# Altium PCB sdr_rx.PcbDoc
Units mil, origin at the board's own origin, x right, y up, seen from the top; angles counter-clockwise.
Board outline 6000 x 4000 mil, 2 copper layers (Top Layer, Bottom Layer); 9 components, 22 nets, 293 pads, 0 vias.
Unrouted connection lines stored in the file: 7.
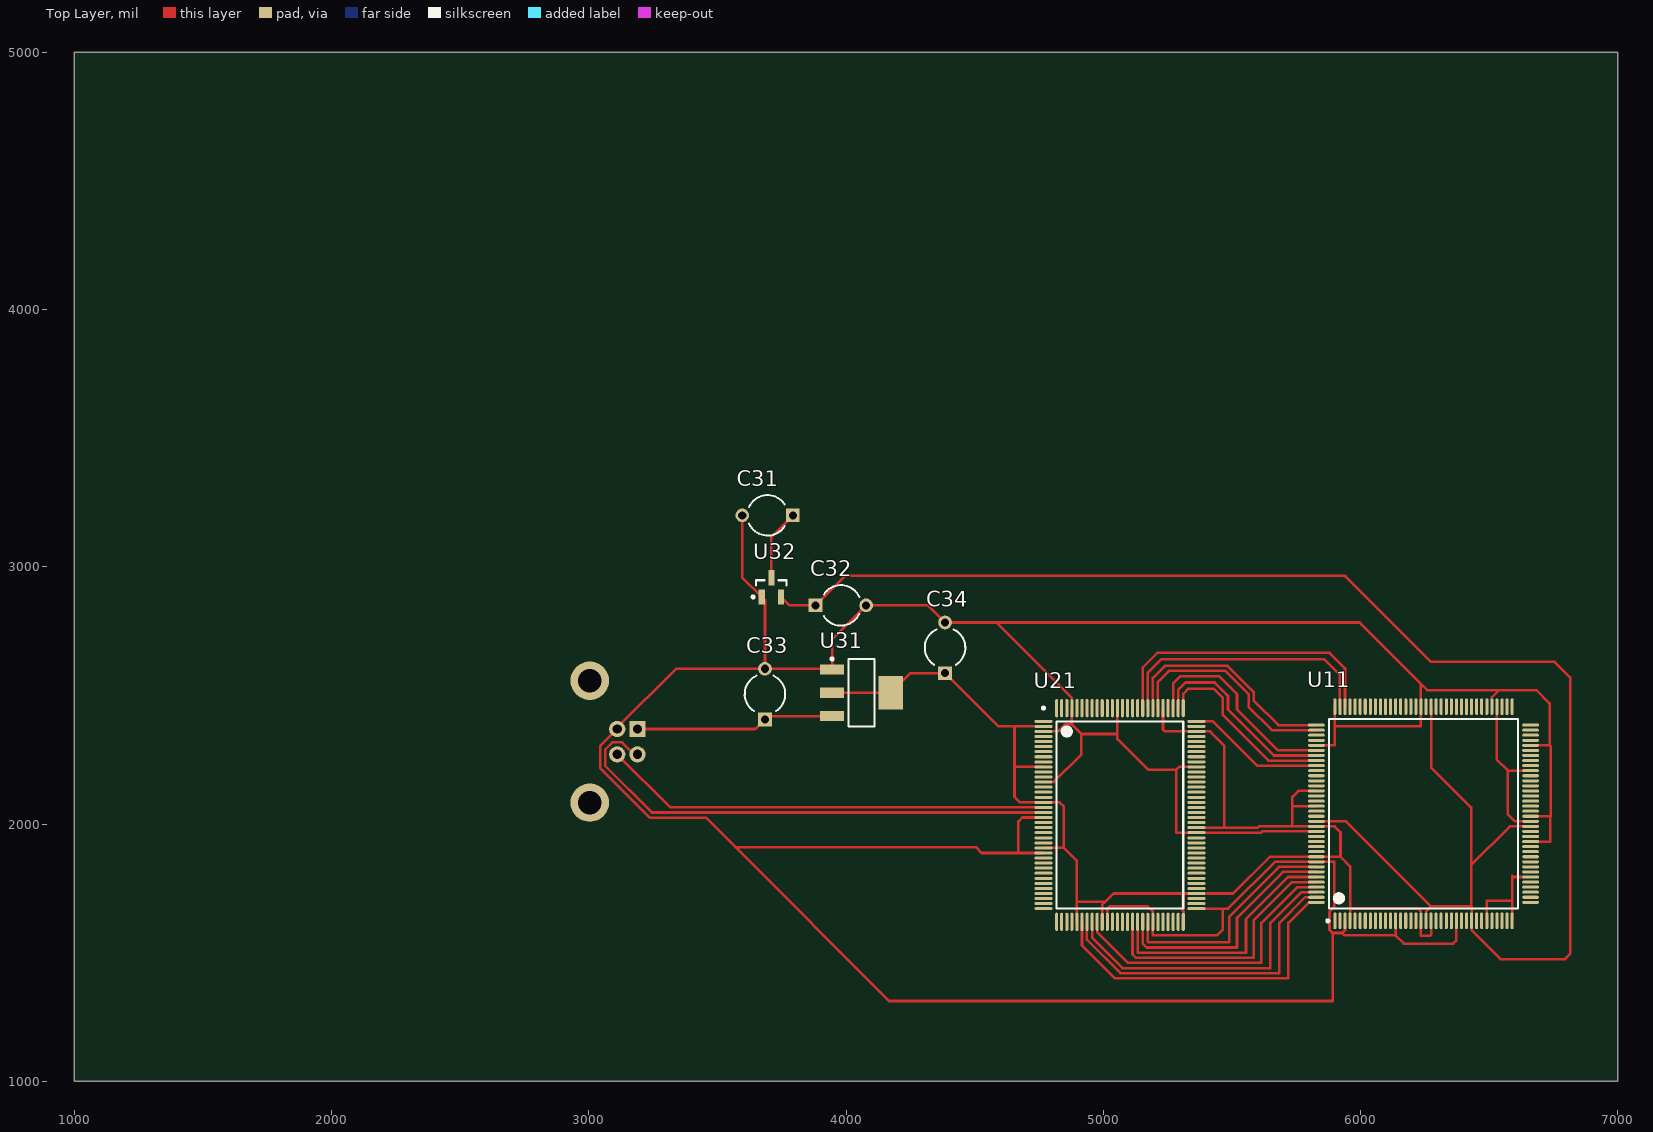
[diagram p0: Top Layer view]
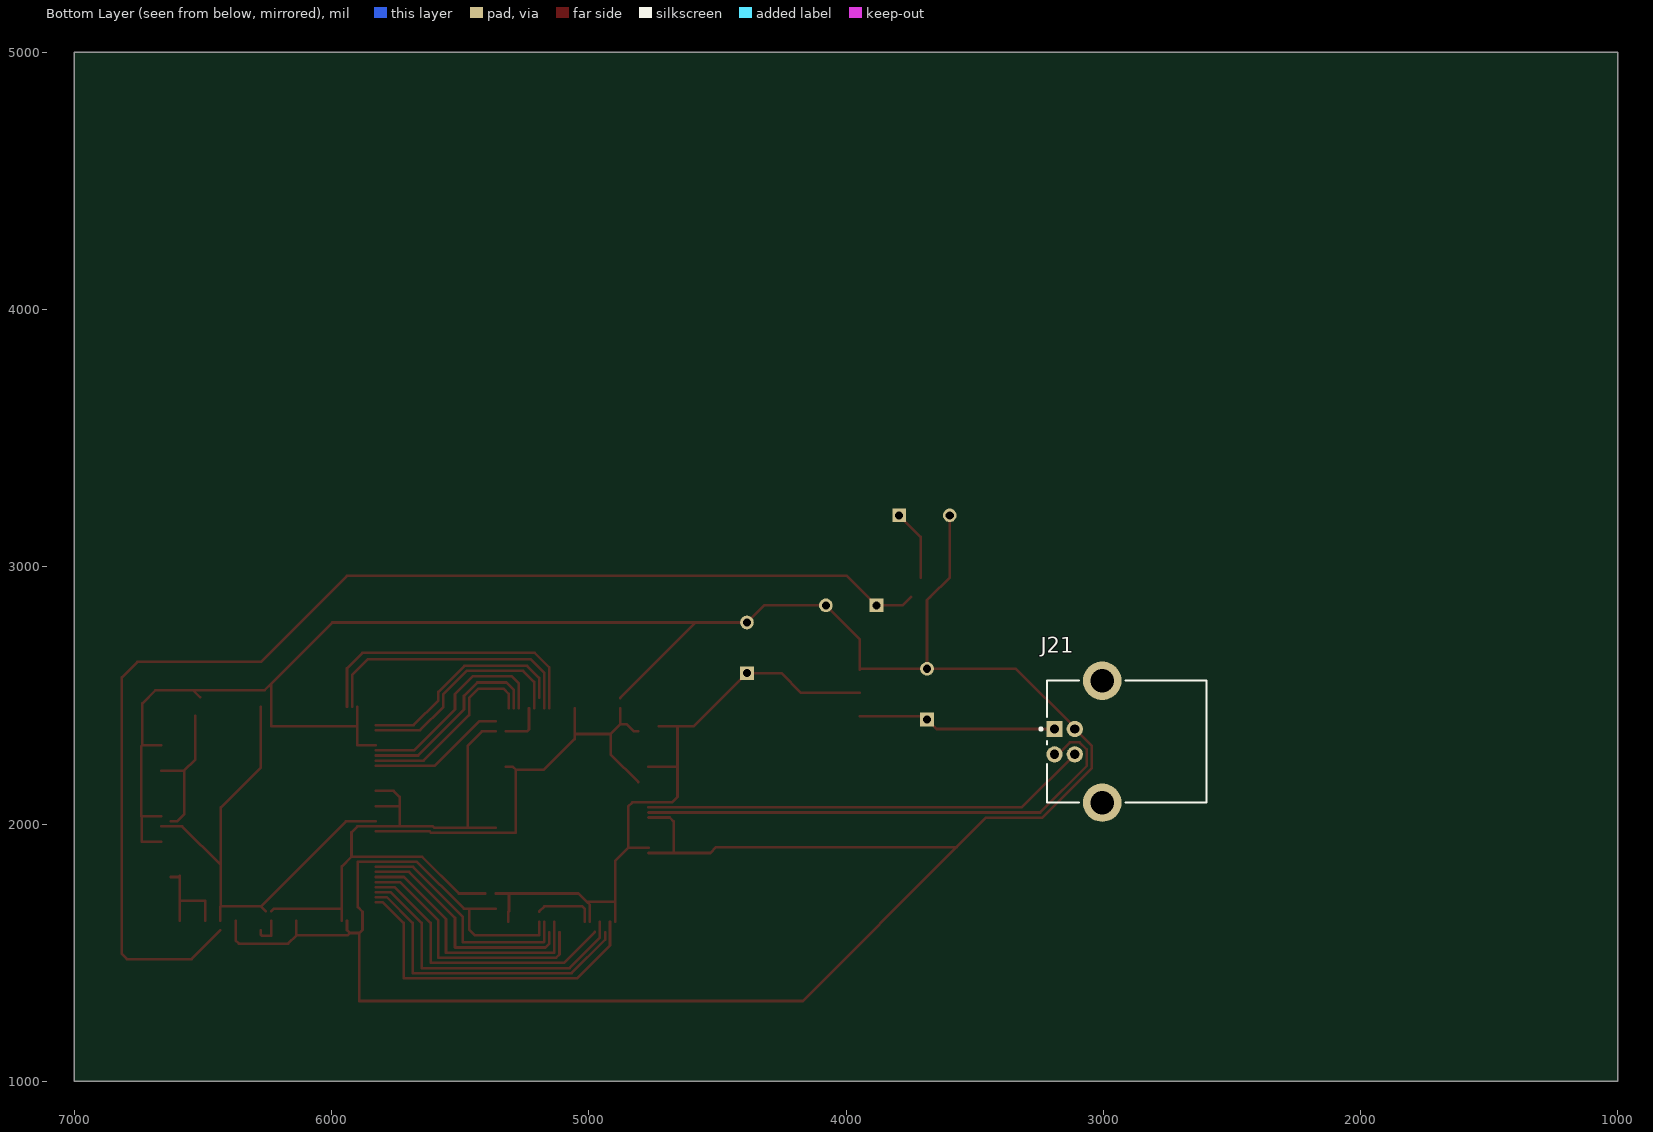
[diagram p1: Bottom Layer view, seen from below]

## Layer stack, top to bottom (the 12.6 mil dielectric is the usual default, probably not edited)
Top Layer: signal copper 1.4
Dielectric: dielectric 12.6, FR-4, Dk 4.8
Bottom Layer: signal copper 1.4

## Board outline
1000,1000 7000,1000 7000,5000 1000,5000

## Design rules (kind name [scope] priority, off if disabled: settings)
Clearance [All] p1: gap=10
PolygonConnect [All] p1: connectstyle=Relief reliefconductorwidth=10 reliefentries=4 polygonreliefangle="90 Angle"
RoomDefinition usbif [InComponentClass('usbif')] p1: confinementstyle=ConfineIn formatcopy=TRUE lockcomponents=FALSE outline 7045,2595 7745,2595 7745,3635 7045,3635
RoomDefinition power [InComponentClass('power')] p2: confinementstyle=ConfineIn formatcopy=TRUE lockcomponents=FALSE outline 7045,2145 9430,2145 9430,2545 7045,2545
RoomDefinition fpga [InComponentClass('fpga')] p3: confinementstyle=ConfineIn formatcopy=TRUE lockcomponents=FALSE outline 7045,1055 8185,1055 8185,2095 7045,2095
RoutingVias [All] p1: holewidth=28 width=50 viastyle="Through Hole" minholewidth=28 minwidth=50 maxholewidth=28 maxwidth=50
SilkscreenOverComponentPads [All] p1: minsilkscreentomaskgap=10
SolderMaskExpansion [All] p1: expansion=4
Width [All] p1: maxlimit=10 minlimit=10 preferedwidth=10
27 further rules are at their usual default settings.

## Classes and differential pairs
component class usbif: J21 U21
component class power: C31 C32 C33 C34 U31 U32

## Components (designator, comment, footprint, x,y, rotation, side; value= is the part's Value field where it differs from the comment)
C31 "Cap2" CAPR5-4X5 3695,3200 r180 top
C32 "Cap2" CAPR5-4X5 3980,2850 r0 top
C33 "Cap2" CAPR5-4X5 3685,2505 r90 top
C34 "Cap2" CAPR5-4X5 4385,2685 r90 top
J21 "787780-1" 787780 3150,2320 r180 bottom
U11 "XC6SLX9-2TQG144" TSQFP50P2200X2200X160-144N 6245,2040 r90 top
U21 "CY7C68014A-128AXC" A128_N 5065,2035 r0 top
U31 "TLV1117" SOT230P700X180-4N 4060,2510 r0 top
U32 "MCP1700T-1202E/TT" SOT-23-TT3_N 3710,2920 r90 top

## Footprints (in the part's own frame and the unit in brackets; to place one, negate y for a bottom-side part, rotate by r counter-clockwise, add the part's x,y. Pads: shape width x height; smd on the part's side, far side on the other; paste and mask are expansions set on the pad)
787780 [mm] "Connector; USB1.1, Type B, Thru-Hole; 4 Position; Right Angle"
  rect 1.6x1.6 hole 0.92: 1(-1,1.25)
  round 1.6 hole 0.92: 2(-1,-1.25) 3(1,-1.25) 4(1,1.25)
  round 3.8 hole 2.3: 5(3.71,6.02) 6(3.71,-6.02)
  silkscreen extent -2.48,-6.02 13.99,6.02
A128_N [mm] "Thin QFP, 128-Leads, Body 20x14 mm, Pitch 0.5mm, IPC Medium Density"
  oval 1.8x0.3 smd: 1(-7.55,9.25) 2(-7.55,8.75) 3(-7.55,8.25) 4(-7.55,7.75) 5(-7.55,7.25) 6(-7.55,6.75) 7(-7.55,6.25) 8(-7.55,5.75) 9(-7.55,5.25) 10(-7.55,4.75) 11(-7.55,4.25) 12(-7.55,3.75) 13(-7.55,3.25) 14(-7.55,2.75) 15(-7.55,2.25) 16(-7.55,1.75) 17(-7.55,1.25) 18(-7.55,0.75) 19(-7.55,0.25) 20(-7.55,-0.25) 21(-7.55,-0.75) 22(-7.55,-1.25) 23(-7.55,-1.75) 24(-7.55,-2.25) 25(-7.55,-2.75) 26(-7.55,-3.25) 27(-7.55,-3.75) 28(-7.55,-4.25) 29(-7.55,-4.75) 30(-7.55,-5.25) 31(-7.55,-5.75) 32(-7.55,-6.25) 33(-7.55,-6.75) 34(-7.55,-7.25) 35(-7.55,-7.75) 36(-7.55,-8.25) 37(-7.55,-8.75) 38(-7.55,-9.25) 65(7.55,-9.25) 66(7.55,-8.75) 67(7.55,-8.25) 68(7.55,-7.75) 69(7.55,-7.25) 70(7.55,-6.75) 71(7.55,-6.25) 72(7.55,-5.75) 73(7.55,-5.25) 74(7.55,-4.75) 75(7.55,-4.25) 76(7.55,-3.75) 77(7.55,-3.25) 78(7.55,-2.75) 79(7.55,-2.25) 80(7.55,-1.75) 81(7.55,-1.25) 82(7.55,-0.75) 83(7.55,-0.25) 84(7.55,0.25) 85(7.55,0.75) 86(7.55,1.25) 87(7.55,1.75) 88(7.55,2.25) 89(7.55,2.75) 90(7.55,3.25) 91(7.55,3.75) 92(7.55,4.25) 93(7.55,4.75) 94(7.55,5.25) 95(7.55,5.75) 96(7.55,6.25) 97(7.55,6.75) 98(7.55,7.25) 99(7.55,7.75) 100(7.55,8.25) 101(7.55,8.75) 102(7.55,9.25)
  oval 0.3x1.8 smd: 39(-6.25,-10.55) 40(-5.75,-10.55) 41(-5.25,-10.55) 42(-4.75,-10.55) 43(-4.25,-10.55) 44(-3.75,-10.55) 45(-3.25,-10.55) 46(-2.75,-10.55) 47(-2.25,-10.55) 48(-1.75,-10.55) 49(-1.25,-10.55) 50(-0.75,-10.55) 51(-0.25,-10.55) 52(0.25,-10.55) 53(0.75,-10.55) 54(1.25,-10.55) 55(1.75,-10.55) 56(2.25,-10.55) 57(2.75,-10.55) 58(3.25,-10.55) 59(3.75,-10.55) 60(4.25,-10.55) 61(4.75,-10.55) 62(5.25,-10.55) 63(5.75,-10.55) 64(6.25,-10.55) 103(6.25,10.55) 104(5.75,10.55) 105(5.25,10.55) 106(4.75,10.55) 107(4.25,10.55) 108(3.75,10.55) 109(3.25,10.55) 110(2.75,10.55) 111(2.25,10.55) 112(1.75,10.55) 113(1.25,10.55) 114(0.75,10.55) 115(0.25,10.55) 116(-0.25,10.55) 117(-0.75,10.55) 118(-1.25,10.55) 119(-1.75,10.55) 120(-2.25,10.55) 121(-2.75,10.55) 122(-3.25,10.55) 123(-3.75,10.55) 124(-4.25,10.55) 125(-4.75,10.55) 126(-5.25,10.55) 127(-5.75,10.55) 128(-6.25,10.55)
  silkscreen extent -7.67,-9.25 6.25,10.67, body extent -7,-10 7,10, height 1.6
CAPR5-4X5 [mm] "Capacitor; 2 Leads"
  rect 1.35x1.35 hole 0.8: 1(-2.5,0)
  round 1.35 hole 0.8: 2(2.5,0)
  silkscreen extent -1.69,-2 1.82,2
SOT230P700X180-4N [mm] "SOT223, 4-Leads, Body 6.7x7.3mm (max), Pitch 2.30mm, IPC Medium Density"
  rect 2.4x1 smd: 1(-2.9,2.3) 2(-2.9,0) 3(-2.9,-2.3)
  rect 2.4x3.3 smd: 4(2.9,0)
  silkscreen extent -3.02,-3.35 1.3,3.47, body extent -1.85,-3.35 1.85,3.35, height 1.8
SOT-23-TT3_N [mm] "SOT23, 3-Leads, Body 2.9x1.3mm, Pitch 0.95mm, Lead Span 2.4mm, IPC Medium Density"
  rect 1.5x0.6 smd: 1(-0.95,0.95) 2(-0.95,-0.95) 3(0.95,0)
  silkscreen extent -1.07,-1.5 0.7,1.92, body extent -0.7,-1.5 0.7,1.5, height 1.12
TSQFP50P2200X2200X160-144N [mm] "TSQFP, 144-Leads, Body 22.0x22.0mm (max), Pitch 0.50mm, IPC Medium Density"
  oval 1.65x0.3 smd: 1(-10.575,8.75) 2(-10.575,8.25) 3(-10.575,7.75) 4(-10.575,7.25) 5(-10.575,6.75) 6(-10.575,6.25) 7(-10.575,5.75) 8(-10.575,5.25) 9(-10.575,4.75) 10(-10.575,4.25) 11(-10.575,3.75) 12(-10.575,3.25) 13(-10.575,2.75) 14(-10.575,2.25) 15(-10.575,1.75) 16(-10.575,1.25) 17(-10.575,0.75) 18(-10.575,0.25) 19(-10.575,-0.25) 20(-10.575,-0.75) 21(-10.575,-1.25) 22(-10.575,-1.75) 23(-10.575,-2.25) 24(-10.575,-2.75) 25(-10.575,-3.25) 26(-10.575,-3.75) 27(-10.575,-4.25) 28(-10.575,-4.75) 29(-10.575,-5.25) 30(-10.575,-5.75) 31(-10.575,-6.25) 32(-10.575,-6.75) 33(-10.575,-7.25) 34(-10.575,-7.75) 35(-10.575,-8.25) 36(-10.575,-8.75) 73(10.575,-8.75) 74(10.575,-8.25) 75(10.575,-7.75) 76(10.575,-7.25) 77(10.575,-6.75) 78(10.575,-6.25) 79(10.575,-5.75) 80(10.575,-5.25) 81(10.575,-4.75) 82(10.575,-4.25) 83(10.575,-3.75) 84(10.575,-3.25) 85(10.575,-2.75) 86(10.575,-2.25) 87(10.575,-1.75) 88(10.575,-1.25) 89(10.575,-0.75) 90(10.575,-0.25) 91(10.575,0.25) 92(10.575,0.75) 93(10.575,1.25) 94(10.575,1.75) 95(10.575,2.25) 96(10.575,2.75) 97(10.575,3.25) 98(10.575,3.75) 99(10.575,4.25) 100(10.575,4.75) 101(10.575,5.25) 102(10.575,5.75) 103(10.575,6.25) 104(10.575,6.75) 105(10.575,7.25) 106(10.575,7.75) 107(10.575,8.25) 108(10.575,8.75)
  oval 0.3x1.65 smd: 37(-8.75,-10.575) 38(-8.25,-10.575) 39(-7.75,-10.575) 40(-7.25,-10.575) 41(-6.75,-10.575) 42(-6.25,-10.575) 43(-5.75,-10.575) 44(-5.25,-10.575) 45(-4.75,-10.575) 46(-4.25,-10.575) 47(-3.75,-10.575) 48(-3.25,-10.575) 49(-2.75,-10.575) 50(-2.25,-10.575) 51(-1.75,-10.575) 52(-1.25,-10.575) 53(-0.75,-10.575) 54(-0.25,-10.575) 55(0.25,-10.575) 56(0.75,-10.575) 57(1.25,-10.575) 58(1.75,-10.575) 59(2.25,-10.575) 60(2.75,-10.575) 61(3.25,-10.575) 62(3.75,-10.575) 63(4.25,-10.575) 64(4.75,-10.575) 65(5.25,-10.575) 66(5.75,-10.575) 67(6.25,-10.575) 68(6.75,-10.575) 69(7.25,-10.575) 70(7.75,-10.575) 71(8.25,-10.575) 72(8.75,-10.575) 109(8.75,10.575) 110(8.25,10.575) 111(7.75,10.575) 112(7.25,10.575) 113(6.75,10.575) 114(6.25,10.575) 115(5.75,10.575) 116(5.25,10.575) 117(4.75,10.575) 118(4.25,10.575) 119(3.75,10.575) 120(3.25,10.575) 121(2.75,10.575) 122(2.25,10.575) 123(1.75,10.575) 124(1.25,10.575) 125(0.75,10.575) 126(0.25,10.575) 127(-0.25,10.575) 128(-0.75,10.575) 129(-1.25,10.575) 130(-1.75,10.575) 131(-2.25,10.575) 132(-2.75,10.575) 133(-3.25,10.575) 134(-3.75,10.575) 135(-4.25,10.575) 136(-4.75,10.575) 137(-5.25,10.575) 138(-5.75,10.575) 139(-6.25,10.575) 140(-6.75,10.575) 141(-7.25,10.575) 142(-7.75,10.575) 143(-8.25,10.575) 144(-8.75,10.575)
  silkscreen extent -10.7,-9.35 9.35,9.57, body extent -10,-10 10,10, height 1.6

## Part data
C31 C32 C33 C34: "Capacitor"
J21: "USB 1.1, Right Angle, Thru-Hole, B Type, Receptacle, 4 Position, Black"
U21: "EZ-USB FX2LP USB Microcontroller Ideal for Battery Powered Applications,16K RAM, 40 I/Os, 128-Pin TQFP, Pb-Free, Commercial Grade"
U32: "Low Quiescent Current LDO, 3-Pin SOT-23, Extended Temperature, Tape and Reel"

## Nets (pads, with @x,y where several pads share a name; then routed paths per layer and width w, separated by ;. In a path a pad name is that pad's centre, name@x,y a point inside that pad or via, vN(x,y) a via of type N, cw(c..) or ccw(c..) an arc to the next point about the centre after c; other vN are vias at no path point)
1V2: C32.1 U11.19 U11.28 U11.52 U11.89 U11.128 U32.2 | length 6762.7
  Top Layer w10: U32.2 3780,2850 C32.1 3996.57,2965 5940,2965 6274.53,2630.47 6754.53,2630.47 6815,2570 6815,1495 6795,1475 6544.21,1475 6432.01,1587.21 ; U11.128 5944.25,2010.47 6274.73,1680 ; 6255.16,1660.43 6274.73,1680 ; U11.89 6274.53,2220.47 6430,2065 6430,1840 ; U11.28 6432.01,1677.99 6430,1680 ; U11.52 6580.79,1990.79 6430,1840 ; 6274.73,1680 6430,1680 ; 6430,1680 6430,1840
3V3: C34.1 U11.4 U11.18 U11.20 U11.31 U11.36 U11.42 U11.53 U11.63 U11.76 U11.86 U11.90 U11.103 U11.122 U11.125 U11.129 U11.135 U21.2 U21.10 U21.17 U21.26 U21.43 U21.48 U21.64 U21.68 U21.81 U21.100 U21.107 U31.2 U31.4 | length 6503.5
  Top Layer w10: U31.2 U31.4 4250.75,2586.57 C34.1 4592.09,2379.49 4655,2379.49 ; 4728.35,2379.49 4655,2379.49 ; U21.26 4847.05,1907.05 ; U21.10 4657.01,2222.01 4655,2220 ; U21.43 4897.68,1697.68 ; U21.48 4996.1,1686.1 5007.68,1697.68 ; U21.107 5232.32,2367.68 5240.2,2359.8 5322.84,2359.8 ; U21.64@5312.28,1619.65 5312.28,1657.83 5310.12,1660 5310.12,1729.88 ; U21.68 5310.12,1729.88 ; U21.81 5600.79,1985.79 5605.79,1990.79 U11.129 5899.21,1990.79 5922.32,1967.68 5922.32,1872.68 ; U21.100 5415.2,2359.8 5470,2305 5470,1986.1 ; 5401.65,1729.88 5504.88,1729.88 5647.68,1872.68 U11.135 5922.32,1872.68 ; 5735,1991.1 5735,2070 ; U11.125 5735.47,2069.53 5735,2070 ; U11.122 5758.58,2128.58 5735,2105 5735,2070 ; U11.4 5959.57,1669.57 ; U11.18 6235.16,1565.16 6270.16,1565.16 6274.53,1569.53 6274.53,1587.21 ; 6235.16,1660.12 6224.13,1671.14 5961.14,1671.14 5959.57,1669.57 ; U11.31 6491.06,1701.06 6588.43,1701.06 6589.49,1700 ; 6530.43,2419.88 6530.43,2249.57 6572.68,2207.32 ; U11.36 6589.49,1700 ; 6624.57,2010.79 6599.21,2010.79 6572.68,2037.32 6572.68,2207.32 ; 6624.88,1793.94 6595.04,1793.94 6589.49,1799.49 6589.49,1700 ; U11.63 6572.68,2207.32 ; 4655,2220 4655,2379.49 ; 4655,2220 4655,2105 4675.79,2084.21 U21.17 4830.79,2084.21 4847.05,2067.95 4847.05,1907.05 ; 4847.05,1907.05 4897.68,1856.42 4897.68,1697.68 ; 4897.68,1697.68 5007.68,1697.68 ; 5007.68,1697.68 5039.88,1729.88 5310.12,1729.88 ; 5922.32,1872.68 5959.57,1835.43 5959.57,1669.57
DATA0: U11.144 U21.44 | length 1304.5
  Top Layer w10: U21.44 4917.36,1527.64 5045,1400 5720,1400 5720,1615 5800.51,1695.51 U11.144
DATA1: U11.143 U21.45 | length 1212.2
  Top Layer w10: 4936.73,1579.92 4936.73,1549.98 5066.72,1420 5685,1420 5685,1615 5785.2,1715.2 U11.143
DATA2: U11.142 U21.46 | length 1207
  Top Layer w10: U21.46 4956.73,1558.27 5075,1440 5650,1440 5650,1615 5769.88,1734.88 U11.142
DATA3: U11.141 U21.47 | length 1114.9
  Top Layer w10: 4976.42,1580.24 5096.66,1460 5615,1460 5615,1615 5754.57,1754.57 U11.141
DATA4: U11.140 U21.54 | length 1014
  Top Layer w10: 5113.9,1579.92 5113.9,1492.82 5126.72,1480 5585,1480 5585,1625 5734.25,1774.25 U11.140
DATA5: U11.139 U21.55 | length 1011.7
  Top Layer w10: U21.55 5133.9,1501.1 5135,1500 5555,1500 5555,1630 5718.94,1793.94 U11.139
DATA6: U11.138 U21.56 | length 915.5
  Top Layer w10: 5153.27,1579.92 5153.27,1534.98 5168.25,1520 5520,1520 5520,1635 5698.62,1813.62 U11.138
DATA7: U11.137 U21.57 | length 913.2
  Top Layer w10: U21.57 5173.27,1543.27 5176.54,1540 5490,1540 5490,1640 5683.31,1833.31 U11.137
DATA8: U11.117 U21.102 | length 537.7
  Top Layer w10: U21.102 5425.83,2399.17 5597.99,2227.01 U11.117
DATA9: U11.116 U21.103 | length 735.5
  Top Layer w10: U21.103 5311.06,2506.06 5330,2525 5430,2525 5465,2490 5465,2423.39 5641.69,2246.69 U11.116
DATA10: U11.115 U21.104 | length 768.9
  Top Layer w10: U21.104 5291.38,2521.38 5320,2550 5433.28,2550 5485,2498.28 5485,2445 5663.62,2266.38 U11.115
DATA11: U11.114 U21.105 | length 819.9
  Top Layer w10: U21.105 5271.69,2546.69 5300,2575 5450,2575 5520,2505 5520,2445 5678.94,2286.06 U11.114
DMINUS: J21.2 U21.19 | length 1998.6
  Top Layer w10: J21.2 3176.39,2270.79 3129.89,2317.28 3091.37,2317.28 3064.13,2290.05 3064.13,2225.87 3245.16,2044.84 U21.19
DPLUS: J21.3 U21.18 | length 1742.6
  Top Layer w10: J21.3 3316.89,2064.53 U21.18
GND: C31.2 C32.2 C33.2 C34.2 J21.4 U11.3 U11.13 U11.25 U11.49 U11.54 U11.68 U11.77 U11.91 U11.96 U11.108 U11.113 U11.130 U11.136 U21.3 U21.13 U21.20 U21.27 U21.49 U21.58 U21.65 U21.80 U21.93 U21.116 U21.125 U31.1 U32.1 | length 15783.1
  Top Layer w10: C31.2 3596.57,2958.62 U32.1 3685,2870.2 C33.2 ; U21.27 4670,1887.36 ; U21.20 4685.16,2025.16 4670,2010 4670,1887.36 ; 4807.16,2162.95 4915,2270.79 4915,2350 ; 4807.16,2359.8 4824.8,2359.8 4852.01,2387.01 4877.99,2387.01 ; U21.125 4877.99,2387.01 ; 4877.99,2489.76 4584.33,2783.43 ; U21.49 5015.79,1670.79 5025,1680 5172.01,1680 5192.95,1659.05 ; U21.116 5055.16,2350 ; U21.58 5192.95,1567.05 5442.05,1567.05 5465,1590 5465,1670.83 ; 5322.84,2222.01 5294.8,2222.01 5283.9,2211.1 ; U21.65 5465,1670.83 ; U11.130 5618.9,1971.1 5613.9,1966.1 U21.80 5283.9,1966.1 5283.9,2211.1 ; U11.113 5899.25,2305.75 5899.29,2305.79 5899.29,2381.06 ; U11.108@5899.29,2456.34 5899.29,2381.06 ; U11.3 5939.88,1587.21 5928.86,1576.18 ; U11.13 6136.73,1566.73 ; U11.25 6372.95,1547.95 6360,1535 6168.46,1535 6136.73,1566.73 ; 6510.75,2492.79 6537.95,2520 ; U11.49 6738.27,1931.73 6738.27,2028.58 6739.84,2030.16 ; U11.54 6739.84,2030.16 ; U11.68 6735.75,2305.75 ; 3569.84,1910 4505,1910 4527.64,1887.36 4670,1887.36 ; 3569.84,1910 3455,2024.84 3236.87,2024.84 3044.13,2217.58 3044.13,2302.72 J21.4 3110.63,2374.68 3339.38,2603.43 C33.2 ; 3569.84,1910 4167.99,1311.85 5891.85,1311.85 5891.85,1576.18 ; C33.2 3942.95,2603.43 U31.1 3945.83,2717.4 C32.2 4318.43,2850 C34.2 4584.33,2783.43 ; 4584.33,2783.43 5996.57,2783.43 6235.16,2544.84 ; 4877.99,2387.01 4915,2350 ; 4915,2350 5055.16,2350 ; 5055.16,2350 5055.16,2330.16 5174.21,2211.1 5283.9,2211.1 ; 5465,1670.83 5485.83,1670.83 5667.99,1852.99 U11.136 5897.99,1852.99 5897.99,1677.28 5879.61,1658.9 5879.61,1588.43 5891.85,1576.18 ; 5891.85,1576.18 5928.86,1576.18 ; 5899.29,2381.06 5900.2,2380.16 6235.16,2380.16 U11.91 6235.16,2544.84 ; 5928.86,1576.18 5938.3,1566.73 6136.73,1566.73 ; 6235.16,2544.84 6260,2520 6537.95,2520 ; 6537.95,2520 6685,2520 6735.75,2469.25 6735.75,2305.75 ; 6735.75,2305.75 6739.84,2301.65 6739.84,2030.16
TCK: U11.109 U21.109 | length 848.2
  Top Layer w10: 5192.64,2490.08 5192.64,2567.64 5240,2615 5483.28,2615 5585,2513.28 5585,2480 5680.51,2384.49 U11.109
TDI: U11.110 U21.108 | length 860.5
  Top Layer w10: U21.108 5212.64,2552.64 5255,2595 5475,2595 5565,2505 5565,2455 5655.2,2364.8 U11.110
TDO: U11.106 U21.111 | length 1141.6
  Top Layer w10: U21.111 5153.58,2608.58 5210,2665 5880,2665 5940,2605 5939.88,2604.88 U11.106
TMS: U11.107 U21.110 | length 1054.7
  Top Layer w10: U21.110 5173.27,2588.27 5225,2640 5860,2640 5920.2,2579.8 U11.107
VCC: C31.1 C33.1 J21.1 U31.3 U32.3 | length 1054.4
  Top Layer w10: J21.1 3647.64,2369.21 C33.1 3697.87,2419.45 U31.3 ; U32.3 3710,3116.57 C31.1
pads on no net: J21.5 J21.6 U11.1 U11.2 U11.5 U11.6 U11.7 U11.8 U11.9 U11.10 U11.11 U11.12 U11.14 U11.15 U11.16 U11.17 U11.21 U11.22 U11.23 U11.24 U11.26 U11.27 U11.29 U11.30 U11.32 U11.33 U11.34 U11.35 U11.37 U11.38 U11.39 U11.40 U11.41 U11.43 U11.44 U11.45 U11.46 U11.47 U11.48 U11.50 U11.51 U11.55 U11.56 U11.57 U11.58 U11.59 U11.60 U11.61 U11.62 U11.64 U11.65 U11.66 U11.67 U11.69 U11.70 U11.71 U11.72 U11.73 U11.74 U11.75 U11.78 U11.79 U11.80 U11.81 U11.82 U11.83 U11.84 U11.85 U11.87 U11.88 U11.92 U11.93 U11.94 U11.95 U11.97 U11.98 U11.99 U11.100 U11.101 U11.102 U11.104 U11.105 U11.111 U11.112 U11.118 U11.119 U11.120 U11.121 U11.123 U11.124 U11.126 U11.127 U11.131 U11.132 U11.133 U11.134 U21.1 U21.4 U21.5 U21.6 U21.7 U21.8 U21.9 U21.11 U21.12 U21.14 U21.15 U21.16 U21.21 U21.22 U21.23 U21.24 U21.25 U21.28 U21.29 U21.30 U21.31 U21.32 U21.33 U21.34 U21.35 U21.36 U21.37 U21.38 U21.39 U21.40 U21.41 U21.42 U21.50 U21.51 U21.52 U21.53 U21.59 U21.60 U21.61 U21.62 U21.63 U21.66 U21.67 U21.69 U21.70 U21.71 U21.72 U21.73 U21.74 U21.75 U21.76 U21.77 U21.78 U21.79 U21.82 U21.83 U21.84 U21.85 U21.86 U21.87 U21.88 U21.89 U21.90 U21.91 U21.92 U21.94 U21.95 U21.96 U21.97 U21.98 U21.99 U21.101 U21.106 U21.112 U21.113 U21.114 U21.115 U21.117 U21.118 U21.119 U21.120 U21.121 U21.122 U21.123 U21.124 U21.126 U21.127 U21.128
